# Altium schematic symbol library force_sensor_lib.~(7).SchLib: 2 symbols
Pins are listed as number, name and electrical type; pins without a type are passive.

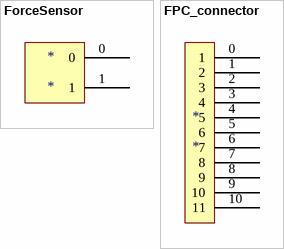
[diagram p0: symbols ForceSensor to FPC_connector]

## ForceSensor
designator *
footprint sensor_connector
pins: 0, 1

## FPC_connector
designator *
pins: 0 1, 1 2, 2 3, 3 4, 4 5, 5 6, 6 7, 7 8, 8 9, 9 10, 10 11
